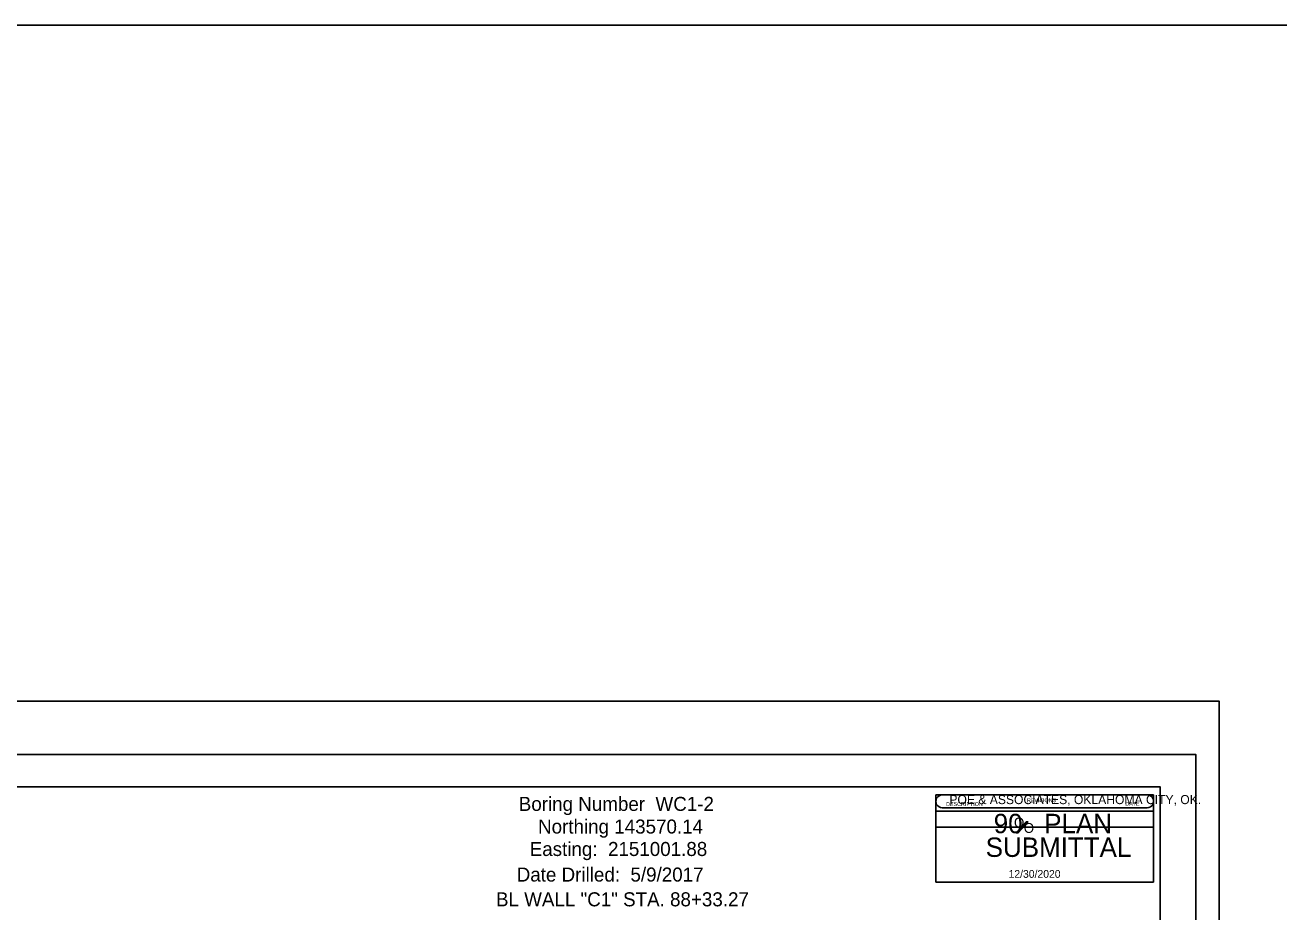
# Model space of a CAD drawing. Extents: x -6 to 173, y 24 to 64.
# Drawn here: x 24.17 to 43.55, y 50.71 to 64.42 of the extents above; entities that cross this region are included whole.
import ezdxf

# ---------------------------------------------------------------- set-up
doc = ezdxf.new("R2010")
doc.units = 0
for name, color, linetype in [('S', 7, 'Continuous'), ('SHT_Plot_Shape_Full', 7, 'Continuous'), ('SHT_Plot_Shape_Half', 7, 'Continuous'), ('SHT_Sheet_Border', 7, 'Continuous'), ('SHT_Stamp_90_Submit', 7, 'Continuous'), ('SHT_Stamp_Rev_Block', 7, 'Continuous')]:
    doc.layers.add(name, color=color, linetype=linetype)

msp = doc.modelspace()

# ---------------------------------------------------------------- linework, layer by layer
at = {"layer": 'S'}
msp.add_lwpolyline([(-6.024, 64.421), (172.576, 64.421), (172.576, 25.783), (-6.024, 25.783)], close=True, dxfattribs=at)
at = {"layer": 'SHT_Plot_Shape_Full'}
msp.add_lwpolyline([(6.624, 53.971), (42.624, 53.971), (42.624, 29.971), (6.624, 29.971)], close=True, dxfattribs=at)
at = {"layer": 'SHT_Plot_Shape_Half'}
msp.add_lwpolyline([(8.262, 53.146), (42.262, 53.146), (42.262, 31.146), (8.262, 31.146)], close=True, dxfattribs=at)
at = {"layer": 'SHT_Sheet_Border'}
msp.add_lwpolyline([(10.212, 52.646), (41.712, 52.646), (41.712, 31.646), (10.212, 31.646)], close=True, dxfattribs=at)
at = {"layer": 'SHT_Stamp_90_Submit'}
for p, q in [((38.343, 52.522), (41.509, 52.522)), ((38.343, 52.322), (41.509, 52.322)), ((38.243, 52.272), (41.609, 52.272)), ((38.243, 51.173), (38.243, 52.272)), ((41.609, 51.173), (41.609, 52.272)), ((39.486, 51.934), (39.641, 52.107)), ((39.486, 51.934), (39.516, 51.934)), ((39.504, 51.934), (39.659, 52.107)), ((39.509, 51.934), (39.664, 52.107)), ((39.516, 51.934), (39.672, 52.107)), ((39.641, 52.107), (39.672, 52.107)), ((38.243, 51.173), (41.609, 51.173))]:
    msp.add_line(p, q, dxfattribs=at)
for centre, start, end in [((38.343, 52.422), 89.9952, 270), ((41.509, 52.422), 270, 90.0048)]:
    msp.add_arc(centre, 0.1, start, end, dxfattribs=at)
at = {"layer": 'SHT_Stamp_Rev_Block'}
for p, q in [((38.243, 52.522), (38.243, 52.022)), ((41.609, 52.522), (38.243, 52.522)), ((41.609, 52.022), (41.609, 52.522)), ((41.609, 52.272), (38.243, 52.272)), ((41.609, 52.022), (38.243, 52.022))]:
    msp.add_line(p, q, dxfattribs=at)

# ---------------------------------------------------------------- texts
for s, p in [('Boring Number  WC1-2', (31.799, 52.275)), ('Northing 143570.14', (32.097, 51.925)), ('Easting:  2151001.88', (31.968, 51.578)), ('Date Drilled:  5/9/2017', (31.767, 51.183)), ('BL WALL "C1" STA. 88+33.27', (31.447, 50.8))]:
    msp.add_text(s, height=0.217).set_placement(p)
at = {"layer": 'SHT_Stamp_90_Submit'}
for s, height, p in [('POE & ASSOCIATES, OKLAHOMA CITY, OK.', 0.14, (38.453, 52.38)), ('90   PLAN', 0.3, (39.138, 51.93)), ('O', 0.153, (39.451, 52.019)), ('O', 0.153, (39.603, 51.935)), ('SUBMITTAL', 0.3, (39.014, 51.564)), ('12/30/2020', 0.12, (39.368, 51.241))]:
    msp.add_text(s, height=height, dxfattribs=at).set_placement(p)
at = {"layer": 'SHT_Stamp_Rev_Block'}
for s, height, p in [('DESCRIPTION', 0.05999, (38.403, 52.351)), ('REVISIONS', 0.06, (39.651, 52.41)), ('DATE', 0.06, (41.172, 52.355))]:
    msp.add_text(s, height=height, dxfattribs=at).set_placement(p)

doc.saveas('drawing.dxf')
